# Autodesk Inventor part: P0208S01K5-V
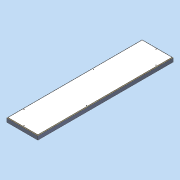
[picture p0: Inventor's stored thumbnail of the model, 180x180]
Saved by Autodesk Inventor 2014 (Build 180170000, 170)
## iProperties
Created: 2011-04
Part Number: P0208S01K5-V
Document SubType Name: Modeling
Designer: david.appleford
Density: 0.215371 g/cm^3
Description: 0.5w x 2w 01 Panel - 6 Locks
Mass: 22000 g
Surface Area: 30384.5 cm^2
Volume: 102149 cm^3
Cost Center: £82.00
Material: Generic
Appearance: Wood (Pine)
Justset: False
Title: 0.5w x 2w 01 Panel - 6 Locks
Author: david.appleford
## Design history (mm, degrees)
sketch "Sketch1"
  geometry: L1 (0, 0)-(610, 0); L2 (610, 0)-(610, 2440); L3 (610, 2440)-(0, 2440); L4 (0, 2440)-(0, 0); L5 (34, 2406)-(576, 2406); L6 (576, 2406)-(576, 34); L7 (576, 34)-(34, 34); L8 (34, 34)-(34, 2406)
  constraints: 16 end point, 4 parallel, 2 perpendicular, 1 horizontal, 3 other
  dimensions: "d0" = 610 distance between parallel lines of L2 L4 (= 0.5 x w); "d1" = 2440 distance between parallel lines of L1 L3 (= 2 x w); "d2" = 34 distance between parallel lines of L5 L3 (= 0.5 x t)
extrude "Extrusion1" new body sketch "Sketch1" distance "d3" = 68 (= t); taper "d4" = 0 deg
sketch "Sketch2"
  geometry: L1 (576, 2406)-(576, 34) reference; L2 (34, 2406)-(576, 2406) reference; L3 (34, 34)-(34, 2406) reference; L4 (576, 34)-(34, 34) reference; L5 (566, 2396)-(566, 44); L6 (566, 44)-(44, 44); L7 (44, 44)-(44, 2396); L8 (44, 2396)-(566, 2396); 1 further point
  constraints: 8 end point, 3 other
  dimensions: "d5" = 10 distance between parallel lines of L8 L2
extrude "Extrusion2" join sketch "Sketch2" distance "d6" = 6 (= sw); taper "d7" = 0 deg
sketch "Sketch3"
  geometry: L1 (-44, 2396)-(-566, 2396) reference; L2 (-566, 2396)-(-566, 44) reference; L3 (-44, 44)-(-44, 2396) reference; L4 (-566, 44)-(-44, 44) reference; 1 further point
extrude "Extrusion3" join sketch "Sketch3" distance "d8" = 6 (= sw); taper "d9" = 0 deg
sketch "Sketch4"
  geometry: L1 (34, 2406)-(576, 2406) reference; L2 (576, 2406)-(576, 34) reference; L3 (576, 34)-(34, 34) reference; L4 (34, 34)-(34, 2406) reference; 7 further points
  constraints: 3 vertical alignment
  dimensions: "d10" = 28 distance from line of point (305, 2378) L1 (= k); "d13" = 28 distance from line of point (62, 305) L4 (= k); "d14" = 305 horizontal distance of point (305, 2378) point (0, 0) (= 0.25 x w); "d16" = 305 vertical distance of point (62, 305) point (0, 0) (= 0.25 x w); "d17" = 1220 distance of point (62, 305) point (62, 1525) (= w); "d19" = 610 vertical distance of point (548, 915) point (62, 305) (= 0.5 x w); "d20" = 1220 distance of point (548, 915) point (548, 2135) (= w); "d29" = 28 distance from line of L3 point (305, 62) (= d13); "d30" = 28 distance from line of L2 point (548, 2135)
hole "Hole1" sketch "Sketch4" at (305, 2378), (62, 1525), (62, 305), (548, 2135), (548, 915), (305, 62) diameter "d22" = 12 (= hd); stored, may be unused: countersink angle "d26" = 90 deg, drill point angle "d28" = 118 deg; dims "d23" = 6, "d24" = 4, "d25" = 2, "d27" = 8
body "Solid1"
node "Projected Loop1"
other parameters: "w" = 1220 [user parameter; used in 7 equation terms], "t" = 68 [user parameter; used in 2 equation terms], "e" = 16 [user parameter], "sw" = 6 [user parameter; used in 2 equation terms], "sc" = 9 [user parameter], "sf" = 12 [user parameter], "k" = 28 [user parameter; used in 2 equation terms], "hd" = 12 [user parameter; used in 1 equation term]
